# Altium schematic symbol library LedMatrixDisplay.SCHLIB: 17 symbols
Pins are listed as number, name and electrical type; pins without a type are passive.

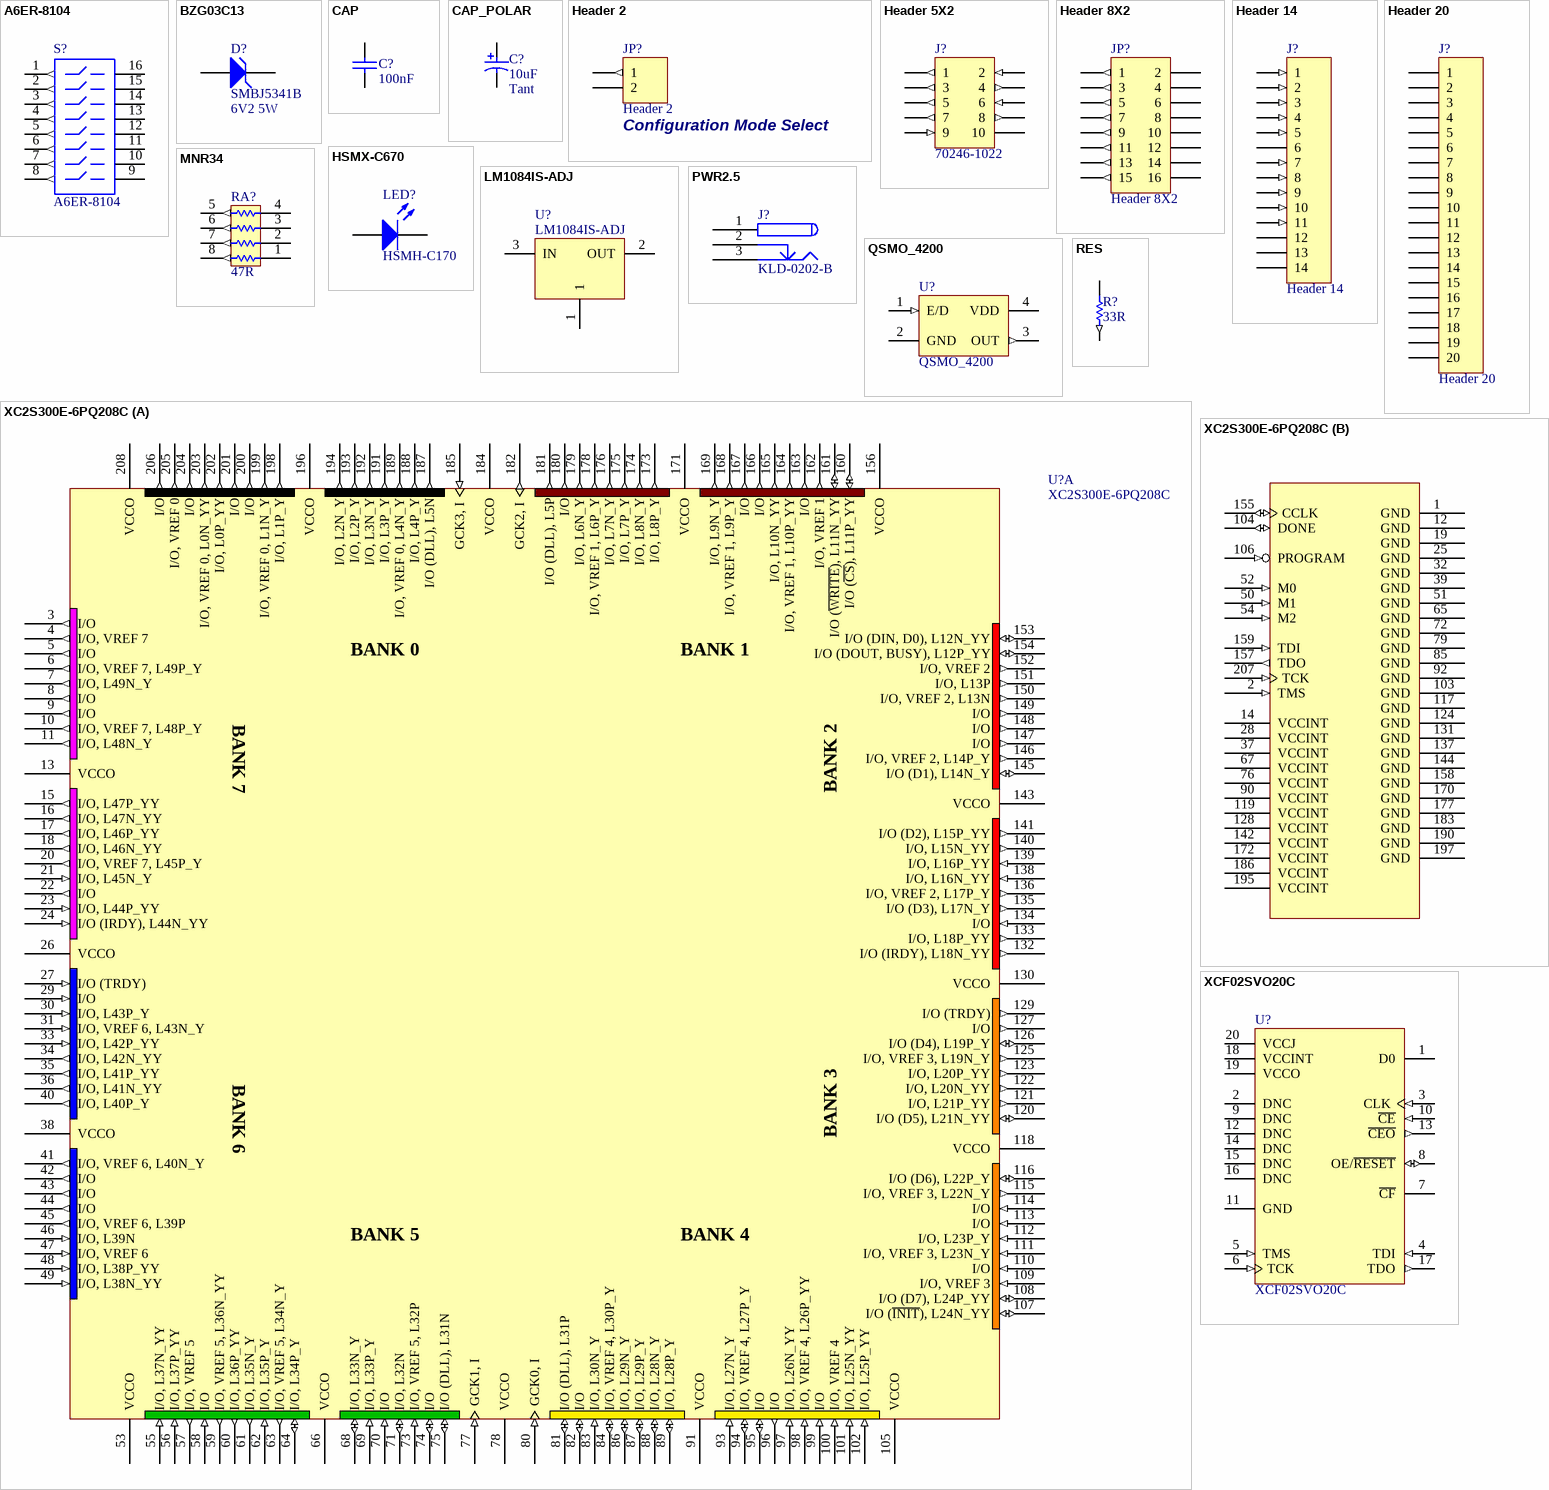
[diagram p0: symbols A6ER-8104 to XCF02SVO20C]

## A6ER-8104
designator S?
DIP Switch Side actuator long liver Piano Key; Manufacturer: Generic Components; Fitted: True
footprint DIP-16-KEY
simulation model dpsw8 (Spice Subcircuit)
pins: 1 (out), 2 (out), 3 (out), 4 (out), 5 (out), 6 (out), 7 (out), 8 (out), 9, 10, 11, 12, 13, 14, 15, 16

## BZG03C13
designator D?, comment SMBJ5341B  Part Description: 6V2 5W
Zener Diode, 6.2V, 5W; Manufacturer: Microsemi; Fitted: True
footprint DO214
pins: 1 A, 2 K

## CAP
designator C?, comment 100nF
Capacitor; Fitted: False
footprint CC1005-0402 (0402 Capacitor)
footprint CC1608-0603 (0603 Capacitor)
footprint CC2012-0805
footprint CC3216-1206 (1206 Capacitor)
footprint CC3225-1210 (1210 Capacitor)
pins: 1, 2

## CAP_POLAR
designator C?, comment 10uF  Capacitor Type: Tant
Polar Capacitor; Fitted: True
footprint MCCT-A (3216 Polar Capacitor)
footprint MCCT-B
footprint MCCT-C (6032 Polar Capacitor)
footprint MCCT-D (7343 Polar Capacitor)
pins: 1, 2

## Header 2
designator JP?  Usage: Configuration Mode Select
Header, 2-Pin; Manufacturer: Generic Components; Class I: Connector; Fitted: True
footprint HDR1X2
signal-integrity model Connector
pins: 1 (out), 2

## Header 5X2
designator J?, comment 70246-1022
Header, 5-Pin, Dual row; Manufacturer: Molex; Class I: Connector; Fitted: True
signal-integrity model Connector
footprint HDR2X5_LP
pins: 1 (out), 2 (in), 3 (out), 4 (out), 5 (out), 6 (in), 7 (out), 8 (out), 9 (in), 10 (power)

## Header 8X2
designator JP?
Header, 8-Pin, Dual row; Manufacturer: Generic Components; Class I: Connector
footprint HDR2X8
signal-integrity model Connector
pins: 1 (out), 2, 3 (out), 4, 5 (out), 6, 7 (out), 8, 9 (out), 10, 11 (out), 12, 13 (out), 14, 15 (out), 16

## Header 14
designator J?
Header, 14-Pin; Manufacturer: Generic Components; Class I: Connector
footprint HDR1X14
signal-integrity model Connector
pins: 1 (in), 2 (in), 3 (in), 4 (in), 5 (in), 6, 7 (in), 8 (in), 9 (in), 10 (in), 11 (in), 12, 13, 14

## Header 20
designator J?
Header, 20-Pin; Manufacturer: Generic Components; Class I: Connector
footprint HDR2X10
signal-integrity model Connector
pins: 1, 2, 3, 4, 5, 6, 7, 8, 9, 10, 11, 12, 13, 14, 15, 16, 17, 18, 19, 20

## HSMX-C670
designator LED?, comment HSMH-C170
Typical RED GaAs SMD LED Agilent make; Manufacturer: Generic Components; Class I: Optoelectronic; Fitted: True
footprint SMD _LED
simulation model LED1 (Diode)
pins: 1 A, 2 K

## LM1084IS-ADJ
designator U?
5A Low Dropout Possitive Regulators; Fitted: True
footprint TO-263
pins: 1 "Output", 2 OUT (power) "Output", 3 IN (power) "Input"

## MNR34
designator RA?, comment 47R
3216x4 Resistor Array; Fitted: True
footprint MNR34 (Footprint not found)
pins: 1, 2, 3, 4, 5 (out), 6 (out), 7 (out), 8 (out)

## PWR2.5
designator J?, comment KLD-0202-B
Low Voltage Power Supply Sonnector; Manufacturer: Kycon; Fitted: True
footprint KLD-0202
pins: 1 (power), 2 (power), 3 (power)

## QSMO_4200
designator U?
Surface Mount Crystal Oscillator; Fitted: False
footprint QSMO_4200
pins: 1 E/D (in) "Low Disables Clock", 2 GND (power), 3 OUT (out) "Output", 4 VDD (power)

## RES
designator R?, comment 33R
Resistor; Fitted: False
footprint CC1005-0402 (0402 Resistor)
footprint CC1310-0504 (0504 Resistor)
footprint CC1608-0603 (0603 Resistor)
footprint CC2012-0805
footprint CC3216-1206 (1206 Resistor)
footprint CC3225-1210 (1210 Resistor)
footprint CC4513-1805 (1805 Resistor)
footprint CC2512 (2512 Resistor)
pins: 1, 2 (out)

## XC2S300E-6PQ208C
designator U?
Spartan-IIE 1.8V FPGA, 208-Pin PQFP, Standard Performance, Commercial Grade; Package Information: Latest Revision: ver1.1, Oct-2002; Code - JEDEC: MS-029-FA-1
footprint PQ208 (208-Pin Plastic Quad Flat Pack (PQ208))
3D model XC2S300E-PQ208 (208-Pin Plastic Quad Flat Pack (PQ208))
part A pins: 3 I/O (out), 4 I/O, VREF 7 (out), 5 I/O (out), 6 I/O, VREF 7, L49P_Y (out), 7 I/O, L49N_Y (out), 8 I/O (out), 9 I/O (out), 10 I/O, VREF 7, L48P_Y (out), 11 I/O, L48N_Y (out), 13 VCCO (power), 15 I/O, L47P_YY (out), 16 I/O, L47N_YY (out), 17 I/O, L46P_YY (out), 18 I/O, L46N_YY (out), 20 I/O, VREF 7, L45P_Y (out), 21 I/O, L45N_Y (in), 22 I/O (out), 23 I/O, L44P_YY (in), 24 I/O (IRDY), L44N_YY (in), 26 VCCO (power), 27 I/O (TRDY) (in), 29 I/O (in), 30 I/O, L43P_Y (in), 31 I/O, VREF 6, L43N_Y (in), 33 I/O, L42P_YY (in), 34 I/O, L42N_YY (out), 35 I/O, L41P_YY (out), 36 I/O, L41N_YY (out), 38 VCCO (power), 40 I/O, L40P_Y (out), 41 I/O, VREF 6, L40N_Y (out), 42 I/O (out), 43 I/O (out), 44 I/O (out), 45 I/O, VREF 6, L39P (out), 46 I/O, L39N (in), 47 I/O, VREF 6 (in), 48 I/O, L38P_YY (in), 49 I/O, L38N_YY (in), 53 VCCO (power), 55 I/O, L37N_YY (in), 56 I/O, L37P_YY (in), 57 I/O, VREF 5 (out), 58 I/O (in), 59 I/O, VREF 5, L36N_YY (out), 60 I/O, L36P_YY (out), 61 I/O, L35N_Y (out), 62 I/O, L35P_Y (in), 63 I/O, VREF 5, L34N_Y (out), 64 I/O, L34P_Y (io), 66 VCCO (power), 68 I/O, L33N_Y (io), 69 I/O, L33P_Y (in), 70 I/O (in), 71 I/O, L32N (io), 73 I/O, VREF 5, L32P (in), 74 I/O (io), 75 I/O (DLL), L31N (io), 77 GCK1, I (in), 78 VCCO (power), 80 GCK0, I (in), 81 I/O (DLL), L31P (io), 82 I/O (io), 83 I/O, L30N_Y (in), 84 I/O, VREF 4, L30P_Y (io), 86 I/O, L29N_Y (io), 87 I/O, L29P_Y (io), 88 I/O, L28N_Y (io), 89 I/O, L28P_Y (io), 91 VCCO (power), 93 I/O, L27N_Y (in), 94 I/O, VREF 4, L27P_Y (io), 95 I/O (io), 96 I/O (out), 97 I/O, L26N_YY (in), 98 I/O, VREF 4, L26P_YY (in), 99 I/O (in), 100 I/O, VREF 4 (in), 101 I/O, L25N_YY (in), 102 I/O, L25P_YY (in), 105 VCCO (power), 107 I/O (~{INIT}), L24N_YY (io), 108 I/O (D7), L24P_YY (io), 109 I/O, VREF 3 (in), 110 I/O (in), 111 I/O, VREF 3, L23N_Y (in), 112 I/O, L23P_Y (in), 113 I/O (in), 114 I/O (in), 115 I/O, VREF 3, L22N_Y (out), 116 I/O (D6), L22P_Y (io), 118 VCCO (power), 120 I/O (D5), L21N_YY (io), 121 I/O, L21P_YY (out), 122 I/O, L20N_YY (out), 123 I/O, L20P_YY (out), 125 I/O, VREF 3, L19N_Y (out), 126 I/O (D4), L19P_Y (io), 127 I/O (out), 129 I/O (TRDY) (out), 130 VCCO (power), 132 I/O (IRDY), L18N_YY (out), 133 I/O, L18P_YY (out), 134 I/O (in), 135 I/O (D3), L17N_Y (out), 136 I/O, VREF 2, L17P_Y (out), 138 I/O, L16N_YY (in), 139 I/O, L16P_YY (in), 140 I/O, L15N_YY (out), 141 I/O (D2), L15P_YY (out), 143 VCCO (power), 145 I/O (D1), L14N_Y (io), 146 I/O, VREF 2, L14P_Y (out), 147 I/O (out), 148 I/O (out), 149 I/O (out), 150 I/O, VREF 2, L13N (out), 151 I/O, L13P (out), 152 I/O, VREF 2 (out), 153 I/O (DIN, D0), L12N_YY (io), 154 I/O (DOUT, BUSY), L12P_YY (io), 156 VCCO (power), 160 I/O (~{CS}), L11P_YY (io), 161 I/O (~{WRITE}), L11N_YY (io), 162 I/O, VREF 1 (out), 163 I/O (out), 164 I/O, VREF 1, L10P_YY (out), 165 I/O, L10N_YY (out), 166 I/O (out), 167 I/O (out), 168 I/O, VREF 1, L9P_Y (out), 169 I/O, L9N_Y (out), 171 VCCO (power), 173 I/O, L8P_Y (out), 174 I/O, L8N_Y (out), 175 I/O, L7P_Y (out), 176 I/O, L7N_Y (out), 178 I/O, VREF 1, L6P_Y (out), 179 I/O, L6N_Y (out), 180 I/O (out), 181 I/O (DLL), L5P (out), 182 GCK2, I (out), 184 VCCO (power), 185 GCK3, I (in), 187 I/O (DLL), L5N (out), 188 I/O, L4P_Y (out), 189 I/O, VREF 0, L4N_Y (out), 191 I/O, L3P_Y (out), 192 I/O, L3N_Y (out), 193 I/O, L2P_Y (out), 194 I/O, L2N_Y (out), 196 VCCO (power), 198 I/O, L1P_Y (out), 199 I/O, VREF 0, L1N_Y (out), 200 I/O (out), 201 I/O (out), 202 I/O, L0P_YY (out), 203 I/O, VREF 0, L0N_YY (out), 204 I/O (out), 205 I/O, VREF 0 (out), 206 I/O (out), 208 VCCO (power)
part B pins: 1 GND (power), 2 TMS (in), 12 GND (power), 14 VCCINT (power), 19 GND (power), 25 GND (power), 28 VCCINT (power), 32 GND (power), 37 VCCINT (power), 39 GND (power), 50 M1 (in), 51 GND (power), 52 M0 (in), 54 M2 (in), 65 GND (power), 67 VCCINT (power), 72 GND (power), 76 VCCINT (power), 79 GND (power), 85 GND (power), 90 VCCINT (power), 92 GND (power), 103 GND (power), 104 DONE (io), 106 PROGRAM (in), 117 GND (power), 119 VCCINT (power), 124 GND (power), 128 VCCINT (power), 131 GND (power), 137 GND (power), 142 VCCINT (power), 144 GND (power), 155 CCLK (io), 157 TDO (out), 158 GND (power), 159 TDI (in), 170 GND (power), 172 VCCINT (power), 177 GND (power), 183 GND (power), 186 VCCINT (power), 190 GND (power), 195 VCCINT (power), 197 GND (power), 207 TCK (in)

## XCF02SVO20C
designator U?
XCF00S Series, Platform Flash In-System Programmable Configuration 3.3V PROM, 20-Pin TSOP, 2-Megabit, Commercial Grade; Manufacturer: Xilinx; Package Information: Latest Revision: ver1.0, May-2003; Code - JEDEC: MO-153-AC
footprint VO20 (20-Lead TSOP (VO20))
pins: 1 D0 (hiz) "Serial Data Output, for configuring an FPGA in serial mode.", 2 DNC "Leave Unconnected.", 3 CLK (in) "Configuration Clock Input.", 4 TDI (in) "JTAG Serial Data Input.", 5 TMS (in) "JTAG Mode Select Input.", 6 TCK (in) "JTAG Test Clock Input.", 7 ~{CF} (oc) "Configuration Pulse (Open-Drain Output).", 8 OE/~{RESET} (io) "Output Enable/Reset (Open-Drain I/O).", 9 DNC "Leave Unconnected.", 10 ~{CE} (in) "Chip Enable Input.", 11 GND (power) "Ground", 12 DNC "Leave Unconnected.", 13 ~{CEO} (out) "Chip Enable Output, connects to the CE input of the next PROM in the chain.", 14 DNC "Leave Unconnected.", 15 DNC "Leave Unconnected.", 16 DNC "Leave Unconnected.", 17 TDO (out) "JTAG Serial Data Output.", 18 VCCINT (power) "+3.3V Supply for internal logic.", 19 VCCO (power) "+3.3V, 2.5V, or 1.8V I/O Supply.", 20 VCCJ (power) "+3.3V or 2.5V JTAG Signals I/O Supply."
